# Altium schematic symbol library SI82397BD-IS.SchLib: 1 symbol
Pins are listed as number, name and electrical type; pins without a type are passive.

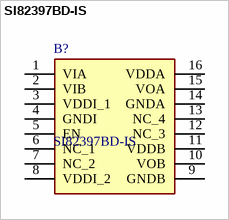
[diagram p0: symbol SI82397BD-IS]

## SI82397BD-IS
designator B?
Gate Drivers 5 kV 8 V UVLO dual isolated gate drive; Manufacturer_Name: Skyworks; Geometry.Height: 2.65mm
footprint SOIC127P1030X265-16N
pins: 1 VIA, 2 VIB, 3 VDDI_1, 4 GNDI, 5 EN, 6 NC_1, 7 NC_2, 8 VDDI_2, 9 GNDB, 10 VOB, 11 VDDB, 12 NC_3, 13 NC_4, 14 GNDA, 15 VOA, 16 VDDA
